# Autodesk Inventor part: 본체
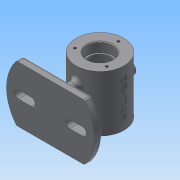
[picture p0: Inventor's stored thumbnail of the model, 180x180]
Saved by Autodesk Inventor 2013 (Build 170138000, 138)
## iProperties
Created: 2017-12
Part Number: 본체
Material: 일반
Document SubType Name: Modeling
Designer: Administrator
Density: 1 g/cm^3
Author: Administrator
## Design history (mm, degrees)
sketch "스케치1"
  geometry: C1 r 30 at (0, 0); 1 further point
  constraints: 1 centre point, 1 coincident
  dimensions: "d0" = 60 diameter of C1
extrude "돌출1" new body sketch "스케치1" stored distance "d2" = 70; taper "d3" = 0 deg
sketch "스케치2"
  geometry: L1 (30, -35)-(-30, -35) reference; L2 (-30, -35)-(-30, 35) reference; L3 (-30, 35)-(30, 35) reference; L4 (30, 35)-(30, -35) reference; L5 (0, 35)-(0, 0); L6 (16, 35)-(16, 23); L7 (16, 23)-(14, 23); L8 (14, 23)-(14, 20); L9 (14, 20)-(25, 20); L10 (25, 20)-(25, 0); L11 (25, 0)-(0, 0); L12 (16, 35)-(0, 35); L13 (0, 0)-(0, -35)
  constraints: 18 end point, 6 parallel, 3 perpendicular, 2 midpoint, 1 point on line
  dimensions: "d4" = 50 diameter of L10 L5; "d6" = 28 diameter of L8 L5; "d8" = 32 diameter of L6 L5; "d9" = 12 distance of L6.start L6.end; "d10" = 20 distance of L9.end L10.end
revolve "회전1" sketch "스케치2" stored, may be unused: angle "d11" = 90 deg
sketch "스케치3"
  geometry: C1 r 16 at (0, 0) reference; 1 further point
  constraints: 1 vertical alignment
  dimensions: "d12" = 23 distance of C1.centre point (0, 23)
hole "구멍1" sketch "스케치3" at (0, 23) diameter "d13" = 3.242; stored, may be unused: countersink angle "d17" = 90 deg, drill point angle "d19" = 118 deg; dims "d14" = 8, "d15" = 4, "d16" = 2, "d18" = 10
node "작업 평면1"
sketch "스케치4"
  geometry: C1 r 8 at (0, 0); 1 further point
  constraints: 1 centre point, 1 coincident
  dimensions: "d24" = 16 diameter of C1
extrude "돌출2" join sketch "스케치4" stored distance "d26" = 70; taper "d27" = 0 deg
hole "구멍2" diameter "d30" = 8; stored, may be unused: countersink angle "d34" = 90 deg, drill point angle "d36" = 0 deg; dims "d28" = 10, "d29" = 10, "d31" = 8, "d32" = 4, "d33" = 2, "d35" = 10
node "작업 평면2"
sketch "스케치5"
  geometry: L1 (61.249, -35)-(42.426, -35); L2 (-61.249, -35)-(-61.249, 35); L3 (-61.249, 35)-(-42.426, 35); L4 (61.249, 35)-(61.249, -35); L5 (61.249, -35)-(-61.249, 35); L6 (-61.249, -35)-(61.249, 35); L7 (-42.426, 35)-(42.426, 35); L8 (-42.426, -35)-(-61.249, -35); L9 (42.426, -35)-(-42.426, -35); L10 (42.426, 35)-(61.249, 35); A1 r 55 centre (0, 0) between (-42.426, 35) and (-42.426, -35); 1 further point
  constraints: 20 end point, 10 parallel, 4 point on circle, 3 horizontal, 3 perpendicular, 2 midpoint, 1 centre point, 1 coincident
  dimensions: "d38" = 110 diameter of A1; "d40" = 70 distance of L2.start L2.end; "d41" = 122.49801 distance of L2.end L4.start
extrude "돌출3" join sketch "스케치5" distance "d42" = 10; taper "d43" = 0 deg
sketch "스케치6"
  geometry: L1 (-40, -5)-(-24, -5); L2 (-24, -5)-(-24, 5); L3 (-24, 5)-(-40, 5); L4 (-40, 5)-(-40, -5); A1 r 55 centre (0, 0) between (-42.426, 35) and (-42.426, -35) reference; A2 r 5 centre (-24, 0) between (-24, 5) and (-24, -5); A3 r 5 centre (-40, 0) between (-40, 5) and (-40, -5); A4 r 5 centre (-40, 0) between (-40, -5) and (-40, 5); A5 r 5 centre (-24, 0) between (-24, -5) and (-24, 5); 1 further point
  constraints: 8 end point, 8 point on circle, 4 centre point, 2 midpoint, 2 parallel, 1 coincident, 1 horizontal, 1 horizontal alignment, 1 perpendicular
  dimensions: "d47" = 16 distance of L2.end L3.end; "d49" = 10 diameter of A2; "d50" = 24 distance from line of A1.centre L2
extrude "돌출4" cut sketch "스케치6" distance "d51" = 10; taper "d52" = 0 deg
sketch "스케치7"
  geometry: L1 (-5, -15)-(5, -15); L2 (5, -15)-(5, 15); L3 (5, 15)-(-5, 15); L4 (-5, 15)-(-5, -15); L5 (-5, -15)-(5, 15); L6 (5, -15)-(-5, 15); A1 r 55 centre (0, 0) between (42.426, -35) and (42.426, 35) reference; 2 further points
  constraints: 12 end point, 4 midpoint, 2 horizontal alignment, 2 parallel, 1 horizontal, 1 perpendicular, 4 other
  dimensions: "d53" = 30 distance of L1.end L2.end; "d55" = 10 distance of L2.end L3.end
extrude "돌출5" join sketch "스케치7" stored distance "d56" = 10; taper "d57" = 0 deg
fillet "모깎기1" dims "d58" = 3
fillet "모깎기2" dims "d59" = 0.3
fillet "모깎기3" dims "d60" = 3
fillet "모깎기4" dims "d61" = 3
chamfer "모따기1" distance "d62" = 1; stored, may be unused: second distance "d63" = 2, angle "d64" = 45 deg
node "작업 평면3"
sketch "스케치8"
  geometry: 2 further points
  constraints: 1 coincident, 1 other
feature "엠보싱1" sketch "스케치8" dims "d66" = 0.5, "d67" = 0
chamfer "모따기2" distance "d68" = 1; stored, may be unused: second distance "d69" = 2, angle "d70" = 45 deg
fillet "모깎기5" dims "d71" = 5
node "솔리드1"
mirror "대칭1"
pattern_circular "원형 패턴1" dims angle "d21" = 360 deg
mirror "대칭2"
mirror "대칭3"
node "절단 모서리 투영1"
other parameters: "d23" = 37, "d37" = -62, "d65" = 154.75
